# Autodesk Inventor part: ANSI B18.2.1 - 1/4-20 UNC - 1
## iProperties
Comments: To add or edit properties for Autodesk Inventor files, use iProperties.
Created: 2004-12
Part Number: ANSI B18.2.1 - 1/4-20 UNC - 1
Vendor: Autodesk Inc.
Document SubType Name: Modeling
Designer: John Blackburn
Material: Default
Description: Hex Cap Screw
Standard: ANSI B18.2.1
Alert: To add or edit properties for Autodesk Inventor files, use iProperties.
Control State: 0
Master: False
Checked Out: False
Shininess: 64.0
Length Units: 11272
Angle Units: 11279
Time Units: 11290
Mass Units: 11286
Length Display Precision: 3
Angle Display Precision: 2
Compacted: True
EGR: 3
Classification: un/spsc 31161513
Density: 0.0
Volumn: 0.0
Area: 0.0
PropertySet Name: Model Information
Author: John Blackburn
Revision Number: 8
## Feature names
1. Body [Revolution]
2. Head [Extrusion]
3. Chamfer1 [Revolution]
4. Chamfer2
